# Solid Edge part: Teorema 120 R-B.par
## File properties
Title: TEOREMA 120/R B
Author: DESYS
Template: Iso Part.par
Last saved by: PIM_1
Revision: 71
Application: Solid Edge
Tipo di contenuto documento: 0
Accuracy: 0.99000000000
Document Number: 8031 120R/B
Revision: 0
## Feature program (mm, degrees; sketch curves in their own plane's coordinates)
sketch for "unnamed Protrusion 1" plane through (10.8674, 10.8674, 0) normal (0, 0, 1) x-axis (1, 0, 0)
  line (-610.8674, 219.1326) -> (589.1326, 219.1326)
  line (589.1326, 219.1326) -> (589.1326, -240.8674)
  line (589.1326, -240.8674) -> (-610.8674, -240.8674)
  line (-610.8674, -240.8674) -> (-610.8674, 219.1326)
  dimension (linear) = 610.8674
  dimension (linear) = 610.8674
  dimension (linear) = 589.1326
  dimension (linear) = 589.1326
extrude "unnamed Protrusion 1" add finite 140 along -normal
sketch for "ScavoEstrusione_1" plane through (0, 0, 0) normal (0, 0, 1) x-axis (1, 0, 0)
  line (0, 0) -> (0, 0)
  line (0, 0) -> (0, 0)
  line (-585, -100) -> (585, -100)
  line (585, -100) -> (585, 215)
  line (-585, 215) -> (585, 215)
  line (-585, 215) -> (-585, -100)
  dimension (linear) = 585
extrude "ScavoEstrusione_1" cut finite 80 along -normal
sketch for "ScavoEstrusione_7" plane through (0, 0, -140) normal (0, 0, -1) x-axis (1, 0, 0)
  line (-500, 110) -> (500, 110)
  line (500, 205) -> (500, 110)
  line (-500, 205) -> (500, 205)
  line (-500, 110) -> (-500, 205)
  dimension (linear) = 500
extrude "ScavoEstrusione_7" cut finite 120 along -normal
sketch for "ScavoEstrusione_8" plane through (0, 0, -140) normal (0, 0, -1) x-axis (1, 0, 0)
  line (-540, -170) -> (340, -170)
  line (-540, 10.1259) -> (-540, -170)
  line (-500, 60.0629) -> (-540, 10.1259)
  line (-500, 110) -> (-500, 60.0629)
  line (-500, 110) -> (500, 110)
  line (500, 110) -> (500, 60.0629)
  line (500, 60.0629) -> (540, 10.1259)
  line (540, 10.1259) -> (540, -170)
  dimension (linear) = 540
  dimension (linear) = 540
  dimension (linear) = 500
extrude "ScavoEstrusione_8" cut finite 40 along -normal
sketch for "v_3" #1 plane through (0, 0, -140) normal (0, 0, -1) x-axis (1, 0, 0)
  line (-540, 9.8811) -> (-540, 205)
  line (-500, 205) -> (-540, 205)
  line (-500, 60.0629) -> (-500, 205)
  line (-500, 60.0629) -> (-540, 9.8811)
  dimension (linear) = 540
  dimension (linear) = 500
  dimension (linear) = 500
  dimension (linear) = 500
sketch for "v_3" #2 plane through (0, 0, -140) normal (0, 0, -1) x-axis (1, 0, 0)
  line (540, 9.8811) -> (540, 205)
  line (500, 205) -> (540, 205)
  line (500, 60.0629) -> (500, 205)
  line (500, 60.0629) -> (540, 9.8811)
extrude "v_3" cut finite 5 along -normal
sketch for "ScavoEstrusione_10" plane through (0, 0, 0) normal (0, 0, 1) x-axis (0, -1, 0)
  line (100, -585) -> (215, -585)
  line (215, -585) -> (215, 585)
  line (215, 585) -> (100, 585)
  line (100, 585) -> (100, -585)
extrude "ScavoEstrusione_10" cut finite 10 along -normal
sketch for "ScavoEstrusione_11" #1 plane through (0, -157.5, -10) normal (0, 0, 1) x-axis (-1, 0, 0)
  circle centre (-310, 0) radius 17.5
sketch for "ScavoEstrusione_11" #2 plane through (0, -157.5, -10) normal (0, 0, 1) x-axis (-1, 0, 0)
extrude "ScavoEstrusione_11" cut finite 665 along -normal
sketch for "unnamed Cutout 1" plane through (0, -100, -45) normal (0, 1, 0) x-axis (-1, 0, 0)
  circle centre (0, 2.5) radius 12.5
extrude "unnamed Cutout 1" cut to key point along -normal
sketch for "ScavoEstrusione_14" #1 plane through (0, -230, -70) normal (0, -1, 0) x-axis (1, 0, 0)
  line (-311.1665, -26.661) -> (-299.7767, -26.661)
  arc centre (-299.7767, -10) radius 16.661 from (-299.7767, 6.661) to (-299.7767, -26.661) cw
  line (-311.1665, 6.661) -> (-299.7767, 6.661)
  arc centre (-311.1665, -10) radius 16.661 from (-311.1665, 6.661) to (-311.1665, -26.661) ccw
sketch for "ScavoEstrusione_14" #2 plane through (0, -230, -70) normal (0, -1, 0) x-axis (1, 0, 0)
  line (311.5714, -26.1032) -> (299.0226, -26.2309)
  arc centre (298.8597, -10.2261) radius 16.0056 from (282.8557, -10) to (299.0226, -26.2309) ccw
  arc centre (299.1889, -10.2308) radius 16.3348 from (282.8557, -10) to (299.0226, 6.1032) cw
  line (311.5714, 6.2309) -> (299.0226, 6.1032)
  arc centre (311.7344, -9.7739) radius 16.0056 from (327.7384, -10) to (311.5714, 6.2309) ccw
  arc centre (311.4052, -9.7692) radius 16.3348 from (311.5714, -26.1032) to (327.7384, -10) ccw
extrude "ScavoEstrusione_14" cut finite 35 along -normal
sketch for "ProtrusioneEstrusa_2" plane through (0, 30, -100) normal (0, 0, -1) x-axis (-1, 0, 0)
  circle centre (0, -15) radius 35
extrude "ProtrusioneEstrusa_2" add finite 30 along +normal
sketch for "ScavoEstrusione_15" plane through (-0.8459, 15.0679, -130) normal (0, 0, -1) x-axis (-1, 0, 0)
  circle centre (-0.8459, -0.0679) radius 22.5
  dimension (linear) = 0.8459
extrude "ScavoEstrusione_15" cut finite 455 along -normal
sketch for "ScavoEstrusione_16" #1 plane through (-500, -132.5315, -77.5) normal (1, 0, 0) x-axis (0, -1, 0)
  circle centre (40.3976, 16.9065) radius 7.5
sketch for "ScavoEstrusione_16" #2 plane through (-500, -132.5315, -77.5) normal (1, 0, 0) x-axis (0, -1, 0)
  circle centre (-753.2679, -1216.4618) radius 7.5
sketch for "ScavoEstrusione_16" #3 plane through (-500, -132.5315, -77.5) normal (1, 0, 0) x-axis (0, -1, 0)
  circle centre (40.3976, 16.9065) radius 7.5
extrude "ScavoEstrusione_16" cut finite 35 along -normal
draft "Spoglia_1"  Angles1 = 5 deg
draft "Spoglia_2"  Angles1 = 5 deg
draft "Spoglia_4"  Angles1 = 4 deg
draft "Spoglia_5"  Angles1 = 4 deg
draft "Spoglia_6"  Angles1 = 4 deg
draft "Spoglia_7"  Angles1 = 5 deg
draft "Spoglia_8"  Angles1 = 5 deg
sketch for "ProtrusioneEstrusa_4" plane through (0, 0, -70) normal (1, 0, 0) x-axis (0, -1, 0)
  line (20, 55) -> (130, 55)
  line (130, 55) -> (130, -50)
  line (130, -50) -> (110, -50)
  line (110, -50) -> (110, 30)
  line (51.3251, 30) -> (110, 30)
extrude "ProtrusioneEstrusa_4" add finite 50 symmetric
sketch for "unnamed Protrusion 2" plane through (-0.8459, -130, -72.5) normal (0, -1, 0) x-axis (-1, 0, 0)
  line (-25.8459, -7.5) -> (-85.8459, -52.5)
extrude "unnamed Protrusion 2" add through along -normal
fillet "Rotondo_4" radius 35
fillet "Rotondo_5" radius 40
fillet "Rotondo_6" radius 7
fillet "Rotondo_8" radius 5
fillet "Rotondo_10" radius 5
fillet "Rotondo_12" radius 5
fillet "Rotondo_13" radius 5
fillet "Rotondo_14" radius 5
fillet "Rotondo_15" radius 10
fillet "Rotondo_16" radius 3
fillet "Rotondo_17" radius 7.5
fillet "Rotondo_18" radius 7.5
fillet "Rotondo_19" radius 7.5
fillet "Rotondo_20" radius 7.5
sketch for "unnamed Cutout 2" plane through (0, 0, -70) normal (1, 0, 0) x-axis (0, -1, 0)
extrude "unnamed Cutout 2" cut finite 40 symmetric
fillet "Rotondo_21" radius 2
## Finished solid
Body 1: solid body, 209 faces, 457 edges, 249 vertices.
  Faces by surface: cylinder 99, plane 38, torus 36, blend 31, sphere 5
  Edges by curve: circle 197, line 184, ellipse 49, intersection 27
Bounding box of the edges (mm; curved faces can reach further): 1200.000 x 460.000 x 140.000, from (-600, -230, -140) to (600, 230, 0).
Cylindrical faces by radius (mm): R2 x8, R5 x38, R7 x4, R7.5 x25, R10 x4, R12.5 x1, R16.0056 x2, R16.3348 x2, R16.661 x2, R17.5 x2, R22.5 x1, R35 x6, R40 x4
Toroidal faces (ring radius, tube radius in mm): R2.5 r7.5 x8, R10 r5 x6, R12 r5 x1, R15.5 r3 x1, R18.0056 r2 x4, R18.3348 r2 x4, R18.661 r2 x4, R20.5 r3 x2, R28 r7 x2, R32.5 r10 x1, R42.5 r7.5 x1, R47.5 r7.5 x2
Spherical faces by radius (mm): R5 x5
Planar faces by outward normal: +x 4, +y 4, +z 4, -x 3, -y 5, -z 8, oblique 10
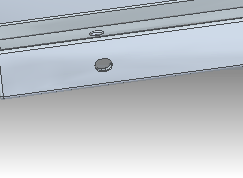
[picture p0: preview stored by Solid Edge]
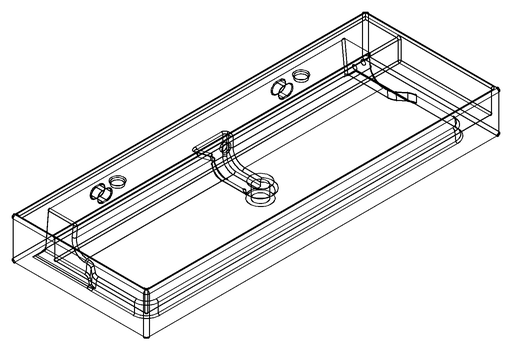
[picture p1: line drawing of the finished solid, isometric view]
